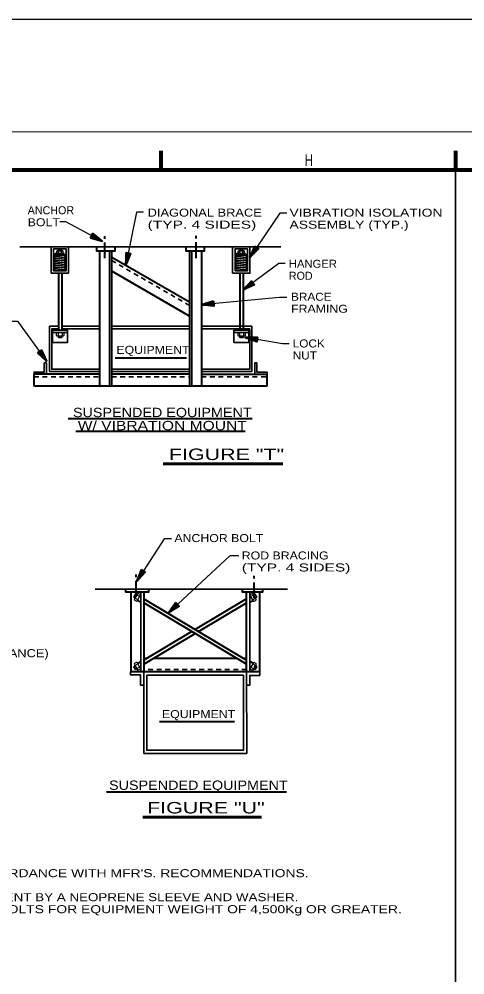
# Model space of a CAD drawing. Extents: x 55 to 190, y 198 to 264.
# Drawn here: x 126.14 to 140.29, y 231.1 to 261.43 of the extents above; entities that cross this region are included whole.
import ezdxf
from ezdxf.enums import TextEntityAlignment as Align

# ---------------------------------------------------------------- set-up
doc = ezdxf.new("R2010")
doc.units = 0
doc.header["$LTSCALE"] = 0.1
doc.linetypes.add('DOT_DASHED', pattern=[7.7, 5, -1.2, 0.3, -1.2])
doc.linetypes.add('SHORT_DASHED', pattern=[2.7, 1.5, -1.2])
for name, color, linetype, lineweight in [('1', 7, 'Continuous', 25), ('2', 7, 'Continuous', 40), ('3', 7, 'Continuous', 25)]:
    doc.layers.add(name, color=color, linetype=linetype, lineweight=lineweight)

msp = doc.modelspace()

# ---------------------------------------------------------------- linework, layer by layer
at = {"layer": '1', "lineweight": 80}
for p, q in [((130.6427, 257.2525), (130.6427, 256.6525)), ((139.9927, 257.2525), (139.9927, 256.6525))]:
    msp.add_line(p, q, dxfattribs=at)
at = {"layer": '1', "lineweight": 13}
msp.add_lwpolyline([(62.4915, 257.8525), (146.5927, 257.8525), (146.5927, 198.4512), (62.4915, 198.4512)], close=True, dxfattribs=at)
at = {"layer": '1', "lineweight": 80}
msp.add_lwpolyline([(65.1915, 256.6525), (145.3927, 256.6525), (145.3927, 199.6512), (65.1915, 199.6512)], close=True, dxfattribs=at)
at = {"layer": '2', "lineweight": 35}
for p, q in [((139.9927, 256.6525), (139.9927, 199.6512)), ((126.1687, 254.2086), (134.4507, 254.2086)), ((129.0064, 254.0808), (129.0064, 249.7811)), ((131.6244, 249.7811), (131.6244, 254.0808)), ((127.1077, 251.684), (127.1077, 250.2483)), ((127.3914, 251.684), (127.1077, 251.684)), ((127.6798, 251.4802), (127.2035, 251.4802)), ((128.7, 251.684), (127.4906, 251.684)), ((128.7, 251.5988), (127.4906, 251.5988)), ((131.5474, 251.684), (129.0836, 251.684)), ((131.5474, 251.5988), (129.0836, 251.5988)), ((133.1482, 251.684), (132.8645, 251.684)), ((133.4366, 251.4802), (132.9603, 251.4802)), ((129.0836, 250.3193), (131.5474, 250.3193)), ((127.1077, 250.2483), (128.7, 250.2483)), ((129.0836, 250.2483), (131.5474, 250.2483)), ((128.5558, 243.3385), (134.664, 243.3385)), ((130.0031, 243.2501), (130.0031, 240.7149)), ((133.4604, 240.7143), (133.4604, 243.2501))]:
    msp.add_line(p, q, dxfattribs=at)
at = {"layer": '2'}
for p, q in [((128.7807, 254.3787), (128.4172, 254.5103)), ((128.7807, 254.3787), (128.427, 254.5293)), ((128.7807, 254.3787), (128.4354, 254.5441)), ((128.4436, 254.56), (128.7807, 254.3787)), ((128.7807, 254.3787), (128.4529, 254.5767)), ((128.7807, 254.3787), (128.4706, 254.6095)), ((133.4646, 253.8686), (133.6332, 254.2166)), ((133.4646, 253.8686), (133.6511, 254.2049)), ((127.2813, 253.9626), (127.6001, 253.9626)), ((127.393, 253.9306), (127.393, 253.9025)), ((127.4927, 253.9427), (127.4927, 253.9141)), ((127.5716, 253.9835), (127.5716, 253.9626)), ((128.7, 249.7811), (128.7, 254.0808)), ((129.0836, 249.7811), (129.0836, 254.0808)), ((129.5266, 253.6332), (129.5469, 254.0192)), ((129.5266, 253.6332), (129.5681, 254.0155)), ((129.5266, 253.6332), (129.5848, 254.0115)), ((129.6022, 254.0083), (129.5266, 253.6332)), ((129.5266, 253.6332), (129.621, 254.0041)), ((129.5266, 253.6332), (129.6575, 253.9967)), ((131.5474, 254.0808), (131.5474, 249.7811)), ((131.9308, 254.0808), (131.9308, 249.7811)), ((133.0381, 253.9626), (133.3569, 253.9626)), ((133.1498, 253.9306), (133.1498, 253.9025)), ((133.2495, 253.9427), (133.2495, 253.9141)), ((133.3283, 253.9835), (133.3283, 253.9626)), ((133.4646, 253.8686), (133.6649, 254.1949)), ((133.6797, 254.1851), (133.4646, 253.8686)), ((133.4646, 253.8686), (133.6956, 254.174)), ((133.4646, 253.8686), (133.7263, 254.1531)), ((127.393, 253.8567), (127.393, 253.8282)), ((127.393, 253.7832), (127.393, 253.7546)), ((127.393, 253.7096), (127.393, 253.6803)), ((127.393, 253.6361), (127.393, 253.6067)), ((127.4927, 253.87), (127.4927, 253.8414)), ((127.4927, 253.7956), (127.4927, 253.766)), ((127.4927, 253.721), (127.4927, 253.6924)), ((127.4927, 253.6474), (127.4927, 253.6189)), ((131.5474, 252.4478), (129.0836, 253.8702)), ((133.1498, 253.8567), (133.1498, 253.8282)), ((133.1498, 253.7832), (133.1498, 253.7546)), ((133.1498, 253.7096), (133.1498, 253.6803)), ((133.1498, 253.6361), (133.1498, 253.6067)), ((133.2495, 253.87), (133.2495, 253.8414)), ((133.2495, 253.7956), (133.2495, 253.766)), ((133.2495, 253.721), (133.2495, 253.6924)), ((133.2495, 253.6474), (133.2495, 253.6189)), ((127.393, 253.5617), (127.393, 253.5329)), ((127.393, 253.4871), (127.393, 253.4577)), ((127.393, 253.363), (127.393, 251.5567)), ((127.4927, 253.5731), (127.4927, 253.5445)), ((127.4927, 253.4995), (127.4927, 253.4702)), ((127.4927, 253.3612), (127.4927, 251.5567)), ((131.5474, 252.0049), (129.0836, 253.4273)), ((133.1498, 253.5617), (133.1498, 253.5329)), ((133.1498, 253.4871), (133.1498, 253.4577)), ((133.1498, 253.363), (133.1498, 251.5567)), ((133.2495, 253.5731), (133.2495, 253.5445)), ((133.2495, 253.4995), (133.2495, 253.4702)), ((133.2495, 253.3612), (133.2495, 251.5567)), ((133.2553, 252.8349), (133.5281, 253.1088)), ((133.2553, 252.8349), (133.5413, 253.0918)), ((133.2553, 252.8349), (133.5511, 253.0781)), ((133.562, 253.0638), (133.2553, 252.8349)), ((133.2553, 252.8349), (133.5734, 253.0482)), ((133.2553, 252.8349), (133.5956, 253.0183)), ((131.9337, 252.364), (132.3089, 252.4568)), ((131.9337, 252.364), (132.3116, 252.4354)), ((131.9337, 252.364), (132.3126, 252.4185)), ((132.3147, 252.4007), (131.9337, 252.364)), ((131.9337, 252.364), (132.3161, 252.3817)), ((131.9337, 252.364), (132.3198, 252.3444)), ((133.6975, 251.2638), (133.3207, 251.3302)), ((133.3207, 251.3302), (133.7038, 251.2979)), ((133.3207, 251.3302), (133.6874, 251.2082)), ((133.3207, 251.3302), (133.694, 251.245)), ((133.3207, 251.3302), (133.7004, 251.2815)), ((133.3207, 251.3302), (133.7072, 251.3191)), ((127.0143, 250.5714), (126.7736, 250.8691)), ((126.7879, 250.8799), (127.0143, 250.5714)), ((127.0143, 250.5714), (126.8035, 250.891)), ((127.0143, 250.5714), (126.8336, 250.913)), ((127.0143, 250.5714), (126.7426, 250.8466)), ((127.0143, 250.5714), (126.7595, 250.8595)), ((129.1895, 250.6809), (131.4578, 250.6809)), ((128.7, 250.1645), (126.6151, 250.1645)), ((126.6151, 249.7811), (126.6151, 250.1645)), ((131.5474, 250.1645), (129.0839, 250.1645)), ((131.9306, 250.1645), (134.0157, 250.1645)), ((134.0157, 249.7811), (134.0157, 250.1645)), ((134.0157, 249.7811), (126.6151, 249.7811)), ((127.7015, 248.7513), (133.5353, 248.7513)), ((127.9441, 248.3513), (133.317, 248.3513)), ((129.8742, 243.5972), (130.0346, 243.9489)), ((129.8742, 243.5972), (130.0528, 243.9378)), ((129.8742, 243.5972), (130.0668, 243.9282)), ((130.0819, 243.9187), (129.8742, 243.5972)), ((129.8742, 243.5972), (130.0978, 243.9079)), ((129.8742, 243.5972), (130.1293, 243.8877)), ((129.6827, 243.2501), (129.6827, 240.7149)), ((129.906, 242.9789), (130.0039, 242.9204)), ((130.1026, 243.2501), (130.1026, 240.7149)), ((130.1026, 243.0329), (133.3609, 241.0866)), ((133.3625, 243.0329), (131.7326, 242.0592)), ((133.3609, 240.7143), (133.3609, 243.2501)), ((133.5572, 242.9789), (133.4593, 242.9204)), ((133.7808, 240.7143), (133.7808, 243.2501)), ((133.3609, 240.9599), (130.1026, 242.9059)), ((130.8902, 242.5958), (131.1326, 242.8972)), ((130.8902, 242.5958), (131.1474, 242.8818)), ((130.8902, 242.5958), (131.1585, 242.8689)), ((131.1709, 242.8559), (130.8902, 242.5958)), ((130.8902, 242.5958), (131.1836, 242.8416)), ((130.8902, 242.5958), (131.209, 242.8143)), ((131.8388, 241.996), (133.3625, 242.9059)), ((131.6266, 241.996), (130.1041, 241.0866)), ((130.1041, 240.9599), (131.7326, 241.9325)), ((129.906, 240.9861), (130.0039, 241.0445)), ((130.1846, 241.1348), (130.1026, 241.1348)), ((133.0662, 241.1348), (130.3952, 241.1348)), ((133.3609, 241.1348), (133.2749, 241.1348)), ((133.5572, 240.9861), (133.4593, 241.0445)), ((133.7808, 240.7149), (129.6827, 240.7149)), ((130.6016, 239.1438), (132.9741, 239.1438)), ((128.9135, 236.9065), (134.6282, 236.9065))]:
    msp.add_line(p, q, dxfattribs=at)
at = {"layer": '2', "linetype": 'DOT_DASHED'}
for p, q in [((128.8625, 253.8419), (128.8625, 254.5468)), ((131.7604, 253.8485), (131.7604, 254.5534)), ((129.8594, 243.0967), (129.8594, 243.8015)), ((133.5996, 243.0525), (133.5996, 243.7573))]:
    msp.add_line(p, q, dxfattribs=at)
at = {"layer": '2', "lineweight": 25}
for p, q in [((127.3985, 253.9028), (127.2813, 253.9173)), ((127.2816, 253.8885), (127.5821, 253.9255)), ((127.2858, 253.9173), (127.5864, 253.9541)), ((127.3371, 253.9924), (127.3371, 254.0623)), ((127.3371, 253.9924), (127.5377, 253.9924)), ((127.3623, 254.0774), (127.5126, 254.0774)), ((127.3869, 253.9924), (127.3869, 254.0623)), ((127.4877, 253.9924), (127.4877, 254.0623)), ((127.4927, 253.9369), (127.5842, 253.9258)), ((127.5377, 253.9924), (127.5377, 254.0618)), ((133.1553, 253.9028), (133.0381, 253.9173)), ((133.0384, 253.8885), (133.3389, 253.9255)), ((133.0426, 253.9173), (133.3432, 253.9541)), ((133.0939, 253.9924), (133.0939, 254.0623)), ((133.0939, 253.9924), (133.2945, 253.9924)), ((133.1191, 254.0774), (133.2694, 254.0774)), ((133.1437, 253.9924), (133.1437, 254.0623)), ((133.2445, 253.9924), (133.2445, 254.0623)), ((133.2495, 253.9369), (133.3411, 253.9258)), ((133.2945, 253.9924), (133.2945, 254.0618)), ((127.2813, 253.8147), (127.5819, 253.8514)), ((127.3985, 253.7549), (127.2813, 253.7694)), ((127.2813, 253.6668), (127.5819, 253.7035)), ((127.3985, 253.607), (127.2813, 253.6213)), ((127.2816, 253.7408), (127.5821, 253.7774)), ((127.2816, 253.5927), (127.5821, 253.6295)), ((127.3985, 253.8292), (127.2818, 253.843)), ((127.3985, 253.681), (127.2818, 253.6953)), ((127.2858, 253.7697), (127.5864, 253.8062)), ((127.2858, 253.6215), (127.5864, 253.6583)), ((127.2861, 253.8432), (127.5866, 253.8803)), ((127.2861, 253.6956), (127.5866, 253.7324)), ((127.5869, 253.8514), (127.4927, 253.8631)), ((127.5864, 253.7774), (127.4927, 253.789)), ((127.5869, 253.7035), (127.4927, 253.7152)), ((127.5864, 253.6295), (127.4927, 253.6411)), ((133.0381, 253.8147), (133.3387, 253.8514)), ((133.1553, 253.7549), (133.0381, 253.7694)), ((133.0381, 253.6668), (133.3387, 253.7035)), ((133.1553, 253.607), (133.0381, 253.6213)), ((133.0384, 253.7408), (133.3389, 253.7774)), ((133.0384, 253.5927), (133.3389, 253.6295)), ((133.1553, 253.8292), (133.0386, 253.843)), ((133.1553, 253.681), (133.0386, 253.6953)), ((133.0426, 253.7697), (133.3432, 253.8062)), ((133.0426, 253.6215), (133.3432, 253.6583)), ((133.0429, 253.8432), (133.3434, 253.8803)), ((133.0429, 253.6956), (133.3434, 253.7324)), ((133.3437, 253.8514), (133.2495, 253.8631)), ((133.3432, 253.7774), (133.2495, 253.789)), ((133.3437, 253.7035), (133.2495, 253.7152)), ((133.3432, 253.6295), (133.2495, 253.6411)), ((127.2406, 253.4397), (127.5821, 253.4816)), ((127.2813, 253.5189), (127.5819, 253.5554)), ((127.3985, 253.4591), (127.2813, 253.4734)), ((127.3985, 253.5331), (127.2818, 253.5474)), ((127.2858, 253.4736), (127.5864, 253.5101)), ((127.2861, 253.5477), (127.5866, 253.5845)), ((127.5869, 253.5554), (127.4927, 253.5673)), ((127.5864, 253.4816), (127.4927, 253.4929)), ((132.9974, 253.4397), (133.3389, 253.4816)), ((133.0381, 253.5189), (133.3387, 253.5554)), ((133.1553, 253.4591), (133.0381, 253.4734)), ((133.1553, 253.5331), (133.0386, 253.5474)), ((133.0426, 253.4736), (133.3432, 253.5101)), ((133.0429, 253.5477), (133.3434, 253.5845)), ((133.3437, 253.5554), (133.2495, 253.5673)), ((133.3432, 253.4816), (133.2495, 253.4929)), ((127.5644, 251.4771), (127.3218, 251.4771)), ((127.3218, 251.4771), (127.3218, 251.3929)), ((127.3824, 251.4771), (127.3824, 251.3924)), ((127.5043, 251.4771), (127.5043, 251.3924)), ((127.5644, 251.4771), (127.5644, 251.3924)), ((133.3212, 251.4771), (133.0786, 251.4771)), ((133.0786, 251.4771), (133.0786, 251.3929)), ((133.1392, 251.4771), (133.1392, 251.3924)), ((133.2612, 251.4771), (133.2612, 251.3924)), ((133.3212, 251.4771), (133.3212, 251.3924)), ((127.534, 251.3739), (127.3519, 251.3739)), ((133.2908, 251.3739), (133.1088, 251.3739)), ((129.8015, 243.0255), (129.8925, 243.1829)), ((129.8755, 242.9474), (129.8023, 242.9898)), ((129.9054, 242.9996), (129.8322, 243.0419)), ((129.8755, 242.9474), (129.9967, 243.1575)), ((129.9666, 243.1051), (129.8933, 243.1475)), ((129.9967, 243.1575), (129.924, 243.1996)), ((133.4665, 243.1575), (133.5392, 243.1996)), ((133.5876, 242.9474), (133.4665, 243.1575)), ((133.4966, 243.1051), (133.5699, 243.1475)), ((133.5577, 242.9996), (133.631, 243.0419)), ((133.6617, 243.0255), (133.5707, 243.1829)), ((133.5876, 242.9474), (133.6609, 242.9898)), ((129.8015, 240.9395), (129.8925, 240.7821)), ((129.8755, 241.0176), (129.8023, 240.9752)), ((129.9054, 240.9654), (129.8322, 240.9231)), ((129.8755, 241.0176), (129.9967, 240.8075)), ((129.9666, 240.8599), (129.8933, 240.8175)), ((133.5876, 241.0176), (133.4665, 240.8075)), ((133.4966, 240.8599), (133.5699, 240.8175)), ((133.5577, 240.9654), (133.631, 240.9231)), ((133.6617, 240.9395), (133.5707, 240.7821)), ((133.5876, 241.0176), (133.6609, 240.9752)), ((129.9967, 240.8075), (129.924, 240.7654)), ((133.4665, 240.8075), (133.5392, 240.7654))]:
    msp.add_line(p, q, dxfattribs=at)
at = {"layer": '2', "linetype": 'SHORT_DASHED', "lineweight": 35}
for p, q in [((129.0836, 253.7662), (131.5474, 252.3438)), ((126.6151, 250.0798), (128.7008, 250.0798)), ((129.0826, 250.0798), (131.5456, 250.0798)), ((131.93, 250.0798), (134.0157, 250.0798)), ((133.3609, 240.7919), (130.1026, 240.7919))]:
    msp.add_line(p, q, dxfattribs=at)
at = {"layer": '2', "lineweight": 60}
for p, q in [((130.7151, 247.3173), (134.5113, 247.3173)), ((130.0729, 236.1011), (133.8387, 236.1011))]:
    msp.add_line(p, q, dxfattribs=at)
at = {"layer": '2', "lineweight": 25}
for points in [[(130.0891, 255.3077), (129.8665, 255.3077), (129.5266, 253.6332)], [(134.6423, 255.2685), (134.4198, 255.2685), (133.4646, 253.8686)], [(127.4329, 255.0069), (127.6163, 255.0069), (128.7807, 254.3787)], [(134.5899, 253.6723), (134.3806, 253.6723), (133.2553, 252.8349)], [(134.6423, 252.5994), (134.4068, 252.5994), (131.9337, 252.364)], [(125.8499, 251.8406), (126.0854, 251.8406), (127.0143, 250.5714)], [(134.7076, 251.1209), (134.4983, 251.1209), (133.3207, 251.3302)], [(130.9786, 244.9371), (130.7428, 244.9371), (129.8742, 243.5972)], [(133.1135, 244.3923), (132.8339, 244.3923), (130.8902, 242.5958)]]:
    msp.add_lwpolyline(points, dxfattribs=at)
at = {"layer": '2'}
for points in [[(128.4079, 254.4931), (128.4809, 254.6277), (128.7807, 254.3787)], [(128.4079, 254.4931), (128.7807, 254.3787), (128.4616, 254.5936)], [(128.5955, 254.2086), (128.5955, 254.0808), (129.1881, 254.0808), (129.1881, 254.2086)], [(131.4347, 254.2086), (131.4347, 254.0808), (132.0274, 254.0808), (132.0274, 254.2086)], [(133.617, 254.2274), (133.7435, 254.1409), (133.4646, 253.8686)], [(133.617, 254.2274), (133.4646, 253.8686), (133.7112, 254.1636)], [(127.5716, 253.9835), (127.2874, 253.9835), (127.2874, 253.9626)], [(129.5279, 254.0232), (129.6779, 253.9924), (129.5266, 253.6332)], [(129.5279, 254.0232), (129.5266, 253.6332), (129.6395, 254.0007)], [(133.3283, 253.9835), (133.0442, 253.9835), (133.0442, 253.9626)], [(133.5165, 253.1244), (133.6078, 253.0013), (133.2553, 252.8349)], [(133.5165, 253.1244), (133.2553, 252.8349), (133.5847, 253.0333)], [(132.3071, 252.4761), (132.3214, 252.3237), (131.9337, 252.364)], [(132.3071, 252.4761), (131.9337, 252.364), (132.3182, 252.3629)], [(133.7104, 251.3384), (133.6834, 251.1876), (133.3207, 251.3302)], [(133.7104, 251.3384), (133.3207, 251.3302), (133.6908, 251.2262)], [(126.727, 250.8349), (126.8506, 250.9251), (127.0143, 250.5714)], [(126.727, 250.8349), (127.0143, 250.5714), (126.8185, 250.9024)], [(130.0181, 243.9597), (130.1465, 243.8761), (129.8742, 243.5972)], [(130.0181, 243.9597), (129.8742, 243.5972), (130.1139, 243.8978)], [(129.517, 243.3385), (129.517, 243.2501), (130.2573, 243.2501), (130.2573, 243.3385)], [(133.2188, 243.3385), (133.2188, 243.2501), (133.8816, 243.2501), (133.8816, 243.3385)], [(131.1194, 242.9114), (131.2231, 242.7987), (130.8902, 242.5958)], [(131.1194, 242.9114), (130.8902, 242.5958), (131.1969, 242.8278)]]:
    msp.add_lwpolyline(points, dxfattribs=at)
at = {"layer": '2', "lineweight": 35}
for points in [[(127.1543, 253.363), (127.7083, 253.363), (127.7083, 254.206), (127.1543, 254.206)], [(132.9111, 253.363), (133.4651, 253.363), (133.4651, 254.206), (132.9111, 254.206)], [(127.2369, 253.4397), (127.6319, 253.4397), (127.6319, 254.1412), (127.2369, 254.1412)], [(132.9937, 253.4397), (133.3887, 253.4397), (133.3887, 254.1412), (132.9937, 254.1412)], [(127.2035, 251.5564), (127.6798, 251.5564), (127.6798, 251.1701), (127.2035, 251.1701)], [(132.9603, 251.5564), (133.4366, 251.5564), (133.4366, 251.1701), (132.9603, 251.1701)], [(130.1928, 240.6045), (130.1928, 238.2278), (133.2619, 238.2278), (133.2619, 240.6045)]]:
    msp.add_lwpolyline(points, close=True, dxfattribs=at)
for points in [[(127.4787, 254.0779), (127.4787, 254.12), (127.3964, 254.12), (127.3964, 254.0779)], [(133.2355, 254.0779), (133.2355, 254.12), (133.1532, 254.12), (133.1532, 254.0779)], [(127.3914, 251.5988), (127.1786, 251.5988), (127.1786, 250.3193), (128.7, 250.3193)], [(131.9308, 250.2483), (133.5329, 250.2483), (133.5329, 251.684), (131.9308, 251.684)], [(131.9308, 250.3193), (133.4617, 250.3193), (133.4617, 251.5988), (131.9308, 251.5988)], [(127.393, 251.3733), (127.393, 251.3226), (127.4927, 251.3226), (127.4927, 251.3733)], [(133.1498, 251.3733), (133.1498, 251.3226), (133.2495, 251.3226), (133.2495, 251.3733)], [(126.6151, 250.1645), (126.6151, 250.2266), (126.94, 250.2266), (126.94, 250.5206), (127.0059, 250.5206), (127.0059, 250.1658)], [(134.015, 250.1639), (134.015, 250.2261), (133.69, 250.2261), (133.69, 250.5203), (133.6239, 250.5203), (133.6239, 250.1653)], [(129.8713, 243.1477), (129.8274, 243.1731), (129.7776, 243.0869), (129.8216, 243.0615)], [(133.5919, 243.1477), (133.6358, 243.1731), (133.6855, 243.0869), (133.6416, 243.0615)], [(129.8713, 240.8173), (129.8274, 240.7919), (129.7776, 240.8781), (129.8216, 240.9035)], [(133.5919, 240.8173), (133.6358, 240.7919), (133.6855, 240.8781), (133.6416, 240.9035)], [(129.6798, 240.7162), (129.6798, 240.6165), (129.9914, 240.6165), (129.9914, 240.2968), (130.1026, 240.2968)], [(130.1026, 240.7149), (130.1026, 238.1259), (133.3641, 238.1259), (133.3609, 240.7143)], [(133.3609, 240.2915), (133.4606, 240.2915), (133.4606, 240.603), (133.7803, 240.603), (133.7803, 240.7143)]]:
    msp.add_lwpolyline(points, dxfattribs=at)
at = {"layer": '2', "lineweight": 25}
for centre, radius, start, end in [((127.3621, 254.0494), 0.028, 27.8877, 152.03419), ((127.4373, 253.9848), 0.0926, 57.00616, 122.94297), ((127.5125, 254.0492), 0.028, 26.78269, 151.8391), ((133.1189, 254.0494), 0.028, 27.8877, 152.03419), ((133.1941, 253.9848), 0.0926, 57.00616, 122.94297), ((133.2693, 254.0492), 0.028, 26.78269, 151.8391), ((127.3522, 251.4083), 0.0339, 206.78269, 331.8391), ((127.4432, 251.4862), 0.1121, 237.00616, 302.94298), ((127.5342, 251.408), 0.0339, 207.8877, 332.03419), ((133.109, 251.4083), 0.0339, 206.78269, 331.8391), ((133.2, 251.4862), 0.1121, 237.00616, 302.94298), ((133.291, 251.408), 0.0339, 207.8877, 332.03419), ((129.8308, 243.0081), 0.0339, 87.8877, 212.03419), ((129.944, 243.0478), 0.1121, 117.00616, 182.94297), ((129.922, 243.1656), 0.0339, 86.78269, 211.8391), ((133.5411, 243.1656), 0.0339, 328.1609, 93.21731), ((133.5192, 243.0478), 0.1121, 357.05703, 62.99384), ((133.6323, 243.0081), 0.0339, 327.96581, 92.1123), ((129.8308, 240.9568), 0.0339, 147.96581, 272.1123), ((129.944, 240.9172), 0.1121, 177.05703, 242.99384), ((133.5192, 240.9172), 0.1121, 297.00616, 2.94297), ((133.6323, 240.9568), 0.0339, 267.8877, 32.03419), ((129.922, 240.7994), 0.0339, 148.1609, 273.21731), ((133.5411, 240.7994), 0.0339, 266.78269, 31.8391)]:
    msp.add_arc(centre, radius, start, end, dxfattribs=at)
for centre, major_axis, start_param, end_param in [((127.2836, 253.9398), (0, -0.0227), 3.2517222, 6.3933148), ((127.5843, 253.9028), (0, 0.0227), 3.2517222, 6.3933148), ((133.0404, 253.9398), (0, -0.0227), 3.2517222, 6.3933148), ((133.3411, 253.9028), (0, 0.0227), 3.2517222, 6.3933148), ((127.2836, 253.7919), (0, -0.0227), 3.2517222, 6.3933148), ((127.2836, 253.644), (0, -0.0227), 3.2517222, 6.3933148), ((127.2839, 253.8658), (0, -0.0227), 3.2517222, 6.3933148), ((127.2839, 253.7179), (0, -0.0227), 3.2517222, 6.3933148), ((127.2839, 253.57), (0, -0.0227), 3.2517222, 6.3933148), ((127.584, 253.8288), (0, 0.0227), 3.2517222, 6.3933148), ((127.584, 253.6809), (0, 0.0227), 3.2517222, 6.3933148), ((127.5843, 253.7549), (0, 0.0227), 3.2517222, 6.3933148), ((127.5843, 253.607), (0, 0.0227), 3.2517222, 6.3933148), ((133.0404, 253.7919), (0, -0.0227), 3.2517222, 6.3933148), ((133.0404, 253.644), (0, -0.0227), 3.2517222, 6.3933148), ((133.0407, 253.8658), (0, -0.0227), 3.2517222, 6.3933148), ((133.0407, 253.7179), (0, -0.0227), 3.2517222, 6.3933148), ((133.0407, 253.57), (0, -0.0227), 3.2517222, 6.3933148), ((133.3408, 253.8288), (0, 0.0227), 3.2517222, 6.3933148), ((133.3408, 253.6809), (0, 0.0227), 3.2517222, 6.3933148), ((133.3411, 253.7549), (0, 0.0227), 3.2517222, 6.3933148), ((133.3411, 253.607), (0, 0.0227), 3.2517222, 6.3933148), ((127.2836, 253.4961), (0, -0.0227), 3.2517222, 6.3933148), ((127.584, 253.533), (0, 0.0227), 3.2517222, 6.3933148), ((127.5843, 253.4591), (0, 0.0227), 3.6938927, 6.3879492), ((133.0404, 253.4961), (0, -0.0227), 3.2517222, 6.3933148), ((133.3408, 253.533), (0, 0.0227), 3.2517222, 6.3933148), ((133.3411, 253.4591), (0, 0.0227), 3.6938927, 6.3879492)]:
    msp.add_ellipse(centre, major_axis=major_axis, ratio=0.9, start_param=start_param, end_param=end_param, dxfattribs=at)
at = {"layer": '2'}
for centre in [(127.584, 253.9767), (133.3408, 253.9767)]:
    msp.add_ellipse(centre, major_axis=(0, 0.0227), ratio=0.9, start_param=3.2517222, end_param=4.0304893, dxfattribs=at)
at = {"layer": '3'}
msp.add_line((62.4915, 261.4312), (146.5927, 261.4312), dxfattribs=at)

# ---------------------------------------------------------------- texts
at = {"layer": '1', "width": 0.7}
msp.add_text('H', height=0.375, dxfattribs=at).set_placement((135.3355, 256.765), align=Align.CENTER)
at = {"layer": '2'}
for s, p in [('ANCHOR', (126.4145, 255.2379)), ('ROD', (134.7029, 253.159))]:
    msp.add_text(s, height=0.254, dxfattribs=at).set_placement(p)
for s, width, p in [('DIAGONAL BRACE', 1.2, (130.2203, 255.1627)), ('VIBRATION ISOLATION', 1.3, (134.7219, 255.1617)), ('BOLT', 1.15, (126.4145, 254.8569)), ('(TYP. 4 SIDES)', 1.45, (130.2203, 254.7817)), ('ASSEMBLY (TYP.)', 1.3, (134.7219, 254.7807)), ('HANGER', 1.05, (134.7029, 253.54)), ('BRACE', 1.1, (134.7727, 252.4931)), ('FRAMING', 1.15, (134.7727, 252.1121)), ('LOCK', 1.1, (134.8251, 251.0101)), ('NUT', 1.1, (134.8251, 250.6291)), ('ANCHOR BOLT', 1.15, (131.0699, 244.8334)), ('ROD BRACING', 1.15, (133.208, 244.2815)), ('(TYP. 4 SIDES)', 1.45, (133.208, 243.9005)), ('GAP(CLEARANCE)', 1.2, (123.4571, 241.1803)), ('1. CLEARANCES AT SIDES FOR SPRING MOUNTED EQUIPMENT AS IN FIG. "R" & "S", SHALL BE IN ACCORDANCE WITH MFR\'S. RECOMMENDATIONS.', 1.3, (103.733, 234.1984)), ('3. IF EQUIPMENT IS MOUNTED ON NEOPRENE PADS, ANCHOR BOLTS SHALL BE ISOLATED FROM EQUIPMENT BY A NEOPRENE SLEEVE AND WASHER.', 1.25, (103.7692, 233.4363)), ('4. PROVIDE A MINIMUM OF (4) 13mm ANCHOR BOLTS FOR EQUIPMENT UP TO 4,500 Kg AND (4) 19mm BOLTS FOR EQUIPMENT WEIGHT OF 4,500Kg OR GREATER.', 1.3, (103.7692, 233.0554))]:
    msp.add_text(s, height=0.254, dxfattribs=dict(at, width=width)).set_placement(p)
for s, height, width, p in [('EQUIPMENT', 0.254, 1.15, (130.3907, 250.8079)), ('SUSPENDED EQUIPMENT', 0.2963, 1.15, (130.6865, 248.799)), ('W/ VIBRATION MOUNT', 0.2963, 1.25, (130.6868, 248.383)), ('FIGURE "T"', 0.3633, 1.4, (132.725, 247.4377)), ('EQUIPMENT', 0.254, 1.15, (131.8374, 239.2475)), ('SUSPENDED EQUIPMENT', 0.2963, 1.15, (131.8311, 236.9697)), ('FIGURE "U"', 0.3633, 1.4, (132.0696, 236.2212))]:
    msp.add_text(s, height=height, dxfattribs=dict(at, width=width)).set_placement(p, align=Align.CENTER)

doc.saveas('drawing.dxf')
